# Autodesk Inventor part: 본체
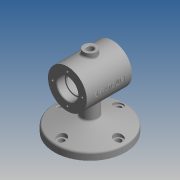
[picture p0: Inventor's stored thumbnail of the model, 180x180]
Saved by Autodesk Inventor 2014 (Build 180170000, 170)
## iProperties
Created: 2018-12
Part Number: 본체
Material: 일반
Document SubType Name: Modeling
Designer: 601-25
Density: 1 g/cm^3
Appearance: 기본값
Mass: 252.795 g
Surface Area: 555.514 cm^2
Volume: 252.795 cm^3
Author: 601-25
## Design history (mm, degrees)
sketch "스케치2"
  geometry: L1 (-35, 0)-(35, 0); L2 (-35, 30)-(35, 30); L3 (-35, 30)-(-35, 16); L4 (-35, 16)-(-23, 16); L5 (-23, 16)-(-23, 14); L6 (-23, 14)-(-20, 14); L7 (-20, 14)-(-20, 25); L8 (-20, 25)-(20, 25); L9 (20, 25)-(20, 14); L10 (20, 14)-(23, 14); L11 (23, 14)-(23, 16); L12 (23, 16)-(35, 16); L13 (35, 16)-(35, 30); 2 further points
  constraints: 26 end point, 6 perpendicular, 5 parallel, 4 collinear, 2 horizontal, 2 vertical alignment, 1 coincident, 1 midpoint
  dimensions: "d0" = 70 distance of L1.start L1.end; "d1" = 60 diameter of L2 L1; "d2" = 32 diameter of L12 L1; "d3" = 28 diameter of L10 L1; "d4" = 50 diameter of L8 L1; "d5" = 12 distance of L3.end L4.end; "d6" = 3 distance of L5.end L6.end
revolve "회전1" sketch "스케치2" stored, may be unused: angle "d7" = 90 deg
chamfer "모따기1" distance "d8" = 1; stored, may be unused: second distance "d9" = 2, angle "d10" = 45 deg
sketch "스케치3"
  geometry: L1 (0, -75)-(-55, -75); L2 (-55, -75)-(-55, -64); L3 (-55, -64)-(0, -49.263); L4 (0, -49.263)-(0, -75); 1 further point
  constraints: 8 end point, 1 horizontal, 1 parallel, 1 perpendicular, 1 vertical alignment
  dimensions: "d11" = 11 distance of L1.end L2.end; "d12" = 55 distance between parallel lines of L2 L4; "d13" = 75 distance from line of L1 point (0, 0); "d14" = 75 deg angle of L3 L2
revolve "회전2" sketch "스케치3" stored, may be unused: angle "d15" = 90 deg
sketch "스케치4"
  geometry: C1 r 55 at (0, 0) reference; C2 r 12 at (0, 0)
  constraints: 1 centre point, 1 coincident
  dimensions: "d16" = 24 diameter of C2
extrude "돌출1" join sketch "스케치4" stored distance "d17" = 10; taper "d18" = 0 deg
fillet "모깎기1" dims "d19" = 0.3, "d20" = 3
sketch "스케치5"
  geometry: C1 r 55 at (0, 0) reference; 1 further point
  constraints: 1 vertical alignment
  dimensions: "d21" = 44 distance of C1.centre point (0, 44)
hole "구멍1" sketch "스케치5" at (0, 44) diameter "d22" = 9; stored, may be unused: countersink angle "d26" = 90 deg, drill point angle "d28" = 0 deg; dims "d23" = 6, "d24" = 4, "d25" = 2, "d27" = 10
hole "구멍2" diameter "d31" = 14; stored, may be unused: countersink angle "d35" = 90 deg, drill point angle "d37" = 0 deg; dims "d29" = 10, "d30" = 10, "d32" = 6, "d33" = 4, "d34" = 2, "d36" = 10
fillet "모깎기2" dims "d41" = 3
sketch "스케치6"
  geometry: C1 r 30 at (0, 0) reference; 1 further point
  constraints: 1 vertical alignment
  dimensions: "d42" = 23 distance of C1.centre point (0, 23)
hole "구멍3" sketch "스케치6" at (0, 23) diameter "d43" = 3.242; stored, may be unused: countersink angle "d47" = 90 deg, drill point angle "d49" = 118 deg; dims "d44" = 8, "d45" = 4, "d46" = 2, "d48" = 10
node "작업 평면1"
sketch "스케치7"
  geometry: C1 r 10 at (0, 0); 1 further point
  constraints: 1 centre point, 1 coincident
  dimensions: "d54" = 20 diameter of C1
extrude "돌출2" join sketch "스케치7" stored distance "d55" = 10; taper "d56" = 0 deg
hole "구멍4" diameter "d59" = 10; stored, may be unused: countersink angle "d63" = 90 deg, drill point angle "d65" = 0 deg; dims "d60" = 10, "d61" = 4, "d62" = 2, "d64" = 10, "d74" = 10, "d75" = 10
chamfer "모따기2" distance "d66" = 1; stored, may be unused: second distance "d67" = 2, angle "d68" = 45 deg
fillet "모깎기3" dims "d69" = 3
node "작업 평면2"
sketch "스케치8"
  geometry: L1 (-35, -30)-(-35, 30) reference; 2 further points
  constraints: 1 other
  dimensions: "d70" = 35 distance from line of point (0, 0) L1; "d71" = 30 vertical distance of L1.end point (0, 0)
feature "엠보싱1" sketch "스케치8" dims "d0" = 70, "d1" = 60, "d2" = 32, "d3" = 28, "d4" = 50, "d5" = 12, "d6" = 3, "d11" = 11, "d12" = 55, "d13" = 75, "d14" = 75 deg, "d72" = 0.5, "d73" = 0
node "솔리드1"
pattern_circular "원형 패턴1" dims angle "d39" = 360 deg
pattern_circular "원형 패턴2" dims angle "d51" = 360 deg
mirror "대칭1"
other parameters: "d53" = 37
